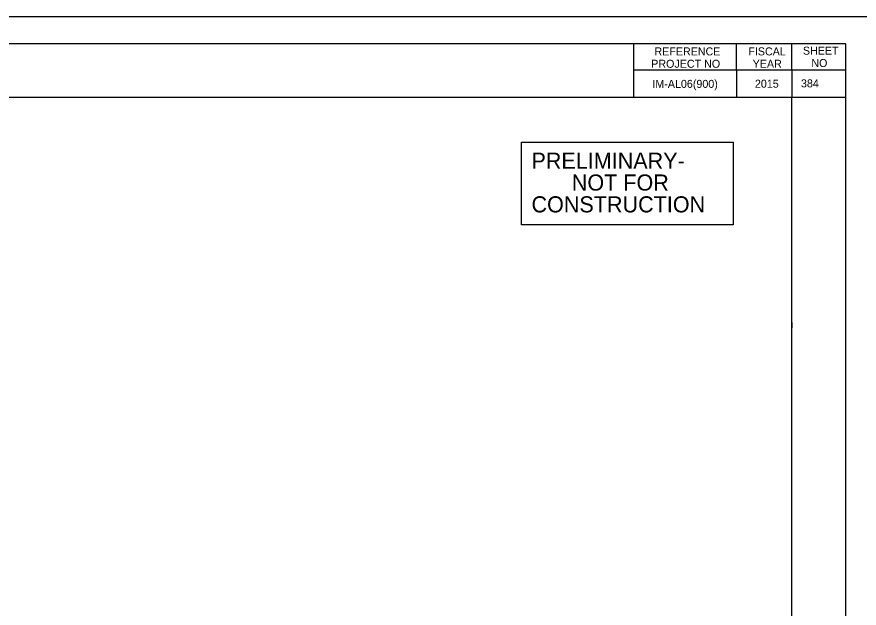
# Model space of a CAD drawing. Extents: x 1797478 to 1804836, y 246529 to 250952.
# Drawn here: x 1802296.8 to 1802453.5, y 250174.4 to 250284.4 of the extents above; entities that cross this region are included whole.
import ezdxf

# ---------------------------------------------------------------- set-up
doc = ezdxf.new("R2010")
doc.units = 0
for name, color, linetype in [('1', 7, 'Continuous'), ('2', 7, 'Continuous'), ('ANNO-SHT', 7, 'Continuous'), ('Level 6', 7, 'Continuous'), ('Level 62', 7, 'Continuous'), ('SHT-BDR', 7, 'Continuous'), ('SHT-BNDRY', 7, 'Continuous')]:
    doc.layers.add(name, color=color, linetype=linetype)

msp = doc.modelspace()

# ---------------------------------------------------------------- linework, layer by layer
at = {"layer": '1'}
msp.add_lwpolyline([(1802390.67, 250261.14), (1802430.07, 250261.14), (1802430.07, 250245.7), (1802390.67, 250245.7)], close=True, dxfattribs=at)
at = {"layer": '2'}
msp.add_lwpolyline([(1802440.97, 250227.57), (1802440.98, 250226.57)], dxfattribs=at)
msp.add_lwpolyline([(1802440.97, 250227.57), (1802440.98, 250226.57)], dxfattribs=at)
at = {"layer": 'Level 6'}
for p, q in [((1802411.55, 250279.42), (1802411.55, 250269.43)), ((1802430.71, 250274.42), (1802430.71, 250279.42)), ((1802441, 250274.55), (1802441, 250279.42)), ((1802451, 250274.48), (1802411.55, 250274.48)), ((1802441, 250274.55), (1802441, 250269.43)), ((1802430.71, 250274.42), (1802430.71, 250269.43)), ((1802451, 250269.43), (1802412.76, 250269.43))]:
    msp.add_line(p, q, dxfattribs=at)
at = {"layer": 'Level 62'}
msp.add_lwpolyline([(1802116, 250064.42), (1802456, 250064.42), (1802456, 250284.42), (1802116, 250284.42)], close=True, dxfattribs=at)
at = {"layer": 'SHT-BDR'}
msp.add_lwpolyline([(1802141, 250079.43), (1802441, 250079.43), (1802441, 250269.43), (1802141, 250269.43)], close=True, dxfattribs=at)
at = {"layer": 'SHT-BNDRY'}
msp.add_lwpolyline([(1802128.5, 250069.42), (1802451, 250069.42), (1802451, 250279.42), (1802128.5, 250279.42)], close=True, dxfattribs=at)

# ---------------------------------------------------------------- texts
at = {"layer": '1'}
for s, p in [('PRELIMINARY-', (1802392.53, 250256.16)), ('NOT FOR', (1802400.04, 250252.1)), ('CONSTRUCTION', (1802392.54, 250248.04))]:
    msp.add_text(s, height=3, dxfattribs=at).set_placement(p)
at = {"layer": 'ANNO-SHT'}
for s, height, p in [('IM-AL06(900)', 1.4899, (1802415.03, 250271.21)), ('2015', 1.49, (1802434.11, 250271.24)), ('  384  ', 1.49, (1802441.57, 250271.3))]:
    msp.add_text(s, height=height, rotation=360, dxfattribs=at).set_placement(p)
at = {"layer": 'Level 6'}
for s, p in [('REFERENCE', (1802415.42, 250277.25)), ('FISCAL', (1802432.89, 250277.25)), ('SHEET', (1802443.04, 250277.39)), ('PROJECT NO', (1802414.82, 250274.95)), ('YEAR', (1802433.69, 250274.95)), ('NO', (1802444.61, 250275.09))]:
    msp.add_text(s, height=1.488, dxfattribs=at).set_placement(p)

doc.saveas('drawing.dxf')
